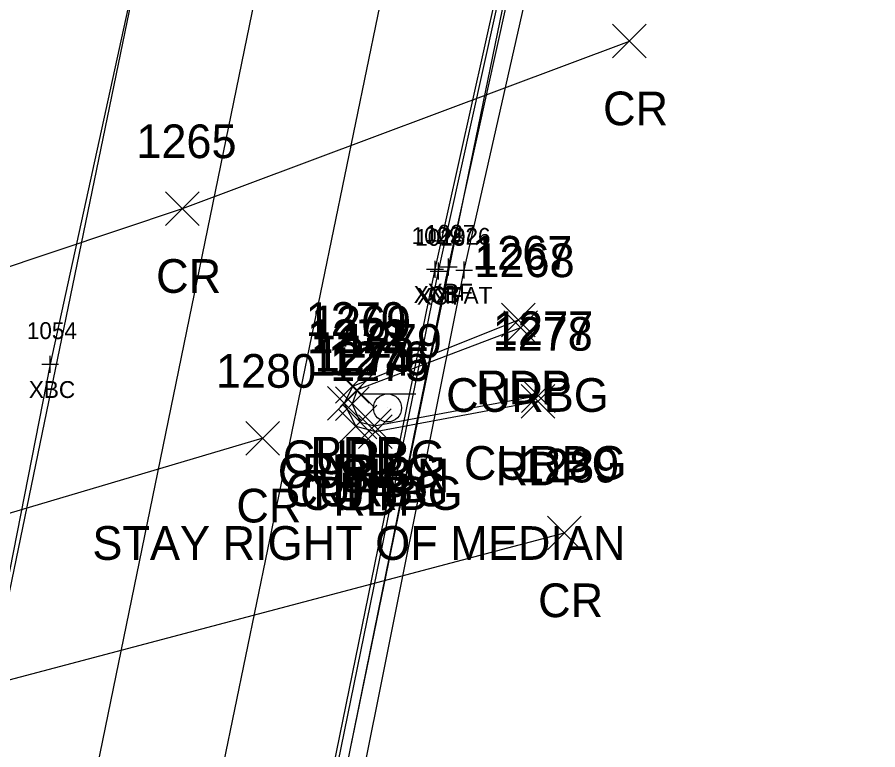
# Model space of a CAD drawing. Extents: x 1683147 to 1683637, y 416837 to 418211.
# Drawn here: x 1683328 to 1683379.1, y 417544.1 to 417587.6 of the extents above; entities that cross this region are included whole.
import ezdxf

# ---------------------------------------------------------------- set-up
doc = ezdxf.new("R2010")
doc.units = 0
for name, color, linetype in [('B_A', 7, 'Continuous'), ('B_I', 7, 'Continuous'), ('B_TIC', 7, 'Continuous'), ('BB', 7, 'Continuous'), ('BDC', 7, 'Continuous'), ('BELB', 7, 'Continuous'), ('BF', 7, 'Continuous'), ('BR', 7, 'Continuous'), ('P_A', 7, 'Continuous'), ('P_I', 7, 'Continuous'), ('P_TIC', 7, 'Continuous'), ('PET', 7, 'Continuous'), ('PRC', 7, 'Continuous'), ('R_A', 7, 'Continuous'), ('R_I', 7, 'Continuous'), ('R_TIC', 7, 'Continuous'), ('RC', 7, 'Continuous'), ('S_A', 7, 'Continuous'), ('S_C', 7, 'Continuous'), ('S_I', 7, 'Continuous'), ('SSGN', 7, 'Continuous')]:
    doc.layers.add(name, color=color, linetype=linetype)

msp = doc.modelspace()

# ---------------------------------------------------------------- linework, layer by layer
at = {"layer": 'B_TIC'}
for p, q in [((1683352.823, 417572.627), (1683352.899, 417572.627)), ((1683353.024, 417572.522), (1683353.1, 417572.522)), ((1683353.628, 417572.765), (1683353.703, 417572.765)), ((1683354.554, 417572.582), (1683354.629, 417572.582)), ((1683329.973, 417566.982), (1683330.049, 417566.982))]:
    msp.add_line(p, q, dxfattribs=at)
for points in [[(1683352.82, 417572.127), (1683352.82, 417573.127)], [(1683353.021, 417572.022), (1683353.021, 417573.022)], [(1683353.624, 417572.265), (1683353.624, 417573.265)], [(1683354.55, 417572.082), (1683354.55, 417573.082)], [(1683352.32, 417572.627), (1683353.32, 417572.627)], [(1683352.521, 417572.522), (1683353.521, 417572.522)], [(1683353.124, 417572.765), (1683354.124, 417572.765)], [(1683354.05, 417572.582), (1683355.05, 417572.582)], [(1683329.97, 417566.482), (1683329.97, 417567.482)], [(1683329.47, 417566.982), (1683330.47, 417566.982)]]:
    msp.add_lwpolyline(points, dxfattribs=at)
at = {"layer": 'BB'}
for points in [[(1683333.132, 417472.311), (1683344.917, 417530.101), (1683362.571, 417615.987), (1683372.841, 417665.754)], [(1683325.054, 417469.66), (1683337.017, 417527.483), (1683354.652, 417613.017), (1683364.916, 417663.193)], [(1683317.14, 417466.973), (1683329.058, 417524.964), (1683346.642, 417610.64), (1683357.082, 417660.489)], [(1683309.186, 417464.354), (1683321.096, 417522.255), (1683338.804, 417607.952), (1683349.063, 417657.849)]]:
    msp.add_lwpolyline(points, dxfattribs=at)
at = {"layer": 'BDC'}
for points in [[(1683333.304, 417470.244), (1683338.538, 417500.213), (1683343.971, 417529.208), (1683352.82, 417572.627), (1683360.871, 417608.794), (1683368.239, 417640.292), (1683375.271, 417668.797)], [(1683333.421, 417470.087), (1683338.691, 417500.106), (1683344.179, 417529.185), (1683353.021, 417572.522), (1683361.056, 417608.824), (1683368.456, 417640.314), (1683375.425, 417668.718)]]:
    msp.add_lwpolyline(points, dxfattribs=at)
at = {"layer": 'BELB'}
msp.add_lwpolyline([(1683351.52, 417660.937), (1683344.246, 417631.627), (1683337.363, 417600.891), (1683329.97, 417566.982), (1683324.712, 417540.29), (1683321.043, 417521.799), (1683314.399, 417485.977), (1683310.141, 417462.954)], dxfattribs=at)
at = {"layer": 'BF'}
msp.add_lwpolyline([(1683335.135, 417469.913), (1683340.482, 417500.015), (1683345.951, 417529.699), (1683354.55, 417572.582), (1683362.731, 417608.707), (1683370.18, 417640.143), (1683377.137, 417668.385)], dxfattribs=at)
at = {"layer": 'BR'}
msp.add_lwpolyline([(1683332.852, 417463.642), (1683334.015, 417470.201), (1683339.17, 417499.968), (1683344.796, 417529.377), (1683353.624, 417572.765), (1683361.607, 417608.917), (1683368.959, 417640.432), (1683375.993, 417668.687), (1683379.103, 417680.373)], dxfattribs=at)
at = {"layer": 'P_TIC'}
for points in [[(1683363.361, 417585.18), (1683365.361, 417587.18)], [(1683365.361, 417585.18), (1683363.361, 417587.18)], [(1683336.826, 417575.227), (1683338.826, 417577.227)], [(1683338.826, 417575.227), (1683336.826, 417577.227)], [(1683356.76, 417568.608), (1683358.76, 417570.608)], [(1683358.76, 417568.608), (1683356.76, 417570.608)], [(1683346.917, 417564.672), (1683348.917, 417566.672)], [(1683348.917, 417564.672), (1683346.917, 417566.672)], [(1683357.925, 417563.791), (1683359.925, 417565.791)], [(1683359.925, 417563.791), (1683357.925, 417565.791)], [(1683346.429, 417563.658), (1683348.429, 417565.658)], [(1683348.429, 417563.658), (1683346.429, 417565.658)], [(1683347.108, 417562.301), (1683349.108, 417564.301)], [(1683349.108, 417562.301), (1683347.108, 417564.301)], [(1683348.282, 417561.991), (1683350.282, 417563.991)], [(1683350.282, 417561.991), (1683348.282, 417563.991)], [(1683341.592, 417561.589), (1683343.592, 417563.589)], [(1683343.592, 417561.589), (1683341.592, 417563.589)], [(1683359.503, 417555.965), (1683361.503, 417557.965)], [(1683361.503, 417555.965), (1683359.503, 417557.965)]]:
    msp.add_lwpolyline(points, dxfattribs=at)
at = {"layer": 'PET'}
msp.add_lwpolyline([(1683357.76, 417569.608), (1683347.917, 417565.672), (1683347.429, 417564.658), (1683348.108, 417563.301), (1683349.282, 417562.991), (1683358.925, 417564.791)], dxfattribs=at)
at = {"layer": 'PRC'}
for points in [[(1683206.154, 417544.862), (1683241.64, 417550.402), (1683274.909, 417557.18), (1683311.228, 417567.333), (1683337.826, 417576.227), (1683364.361, 417586.18)], [(1683342.592, 417562.589), (1683311.955, 417553.502), (1683276.156, 417545.385), (1683245.179, 417538.35), (1683203.393, 417531.667)], [(1683202.452, 417523.569), (1683242.343, 417529.845), (1683281.666, 417537.682), (1683320.124, 417546.282), (1683360.503, 417556.965)]]:
    msp.add_lwpolyline(points, dxfattribs=at)
at = {"layer": 'R_TIC'}
for points in [[(1683356.896, 417568.158), (1683358.896, 417570.158)], [(1683358.896, 417568.158), (1683356.896, 417570.158)], [(1683347.195, 417564.461), (1683349.195, 417566.461)], [(1683349.195, 417564.461), (1683347.195, 417566.461)], [(1683357.95, 417564.124), (1683359.95, 417566.124)], [(1683359.95, 417564.124), (1683357.95, 417566.124)], [(1683346.902, 417563.641), (1683348.902, 417565.641)], [(1683348.902, 417563.641), (1683346.902, 417565.641)], [(1683347.366, 417562.546), (1683349.366, 417564.546)], [(1683349.366, 417562.546), (1683347.366, 417564.546)], [(1683348.219, 417562.334), (1683350.219, 417564.334)], [(1683350.219, 417562.334), (1683348.219, 417564.334)]]:
    msp.add_lwpolyline(points, dxfattribs=at)
at = {"layer": 'RC'}
msp.add_lwpolyline([(1683357.896, 417569.158), (1683348.195, 417565.461), (1683347.902, 417564.641), (1683348.366, 417563.546), (1683349.219, 417563.334), (1683358.95, 417565.124)], dxfattribs=at)
at = {"layer": 'SSGN'}
for p, q in [((1683348.352, 417565.223), (1683351.685, 417565.223)), ((1683349.999, 417564.39), (1683349.999, 417564.39))]:
    msp.add_line(p, q, dxfattribs=at)
msp.add_circle((1683349.999, 417564.39), 0.833, dxfattribs=at)

# ---------------------------------------------------------------- texts
at = {"layer": 'B_A'}
for s, p in [('XCB', (1683351.556, 417570.627)), ('XCT', (1683351.741, 417570.522)), ('XRF', (1683352.384, 417570.765)), ('XFAT', (1683352.806, 417570.582)), ('XBC', (1683328.706, 417564.982))]:
    msp.add_text(s, height=1, dxfattribs=at).set_placement(p)
at = {"layer": 'B_I'}
for s, p in [('1029', (1683351.43, 417574.127)), ('1028', (1683351.635, 417574.022)), ('1027', (1683352.239, 417574.265)), ('1026', (1683353.137, 417574.082)), ('1054', (1683328.584, 417568.482))]:
    msp.add_text(s, height=1, dxfattribs=at).set_placement(p)
at = {"layer": 'P_A'}
for s, p in [('CR', (1683362.794, 417581.18)), ('CR', (1683336.259, 417571.227)), ('RDP', (1683355.248, 417564.608)), ('RDP', (1683345.405, 417560.672)), ('RDP', (1683356.413, 417559.791)), ('RDP', (1683344.918, 417559.658)), ('RDP', (1683345.596, 417558.301)), ('RDP', (1683346.771, 417557.991)), ('CR', (1683341.025, 417557.589)), ('CR', (1683358.937, 417551.965))]:
    msp.add_text(s, height=2, dxfattribs=at).set_placement(p)
at = {"layer": 'P_I'}
for s, p in [('1265', (1683335.086, 417579.227)), ('1267', (1683355.02, 417572.608)), ('1270', (1683345.138, 417568.672)), ('1271', (1683345.304, 417567.658)), ('1278', (1683356.232, 417567.791)), ('1274', (1683345.415, 417566.301)), ('1275', (1683346.59, 417565.991)), ('1280', (1683339.813, 417565.589)), ('1289', (1683357.803, 417559.965))]:
    msp.add_text(s, height=2, dxfattribs=at).set_placement(p)
at = {"layer": 'R_A'}
for p in [(1683353.478, 417564.158), (1683343.777, 417560.461), (1683354.533, 417560.124), (1683343.485, 417559.641), (1683343.948, 417558.546), (1683344.802, 417558.334)]:
    msp.add_text('CURBG', height=2, dxfattribs=at).set_placement(p)
at = {"layer": 'R_I'}
for s, p in [('1268', (1683355.156, 417572.158)), ('1269', (1683345.447, 417568.461)), ('1277', (1683356.257, 417568.124)), ('1272', (1683345.209, 417567.641)), ('1273', (1683345.673, 417566.546)), ('1276', (1683346.471, 417566.334))]:
    msp.add_text(s, height=2, dxfattribs=at).set_placement(p)
at = {"layer": 'S_A'}
msp.add_text('SIGN', height=2, dxfattribs=at).set_placement((1683347.137, 417559.369))
at = {"layer": 'S_C'}
msp.add_text('STAY RIGHT OF MEDIAN', height=2, dxfattribs=at).set_placement((1683332.476, 417555.369))
at = {"layer": 'S_I'}
msp.add_text('1279', height=2, dxfattribs=at).set_placement((1683347.279, 417567.369))

doc.saveas('drawing.dxf')
